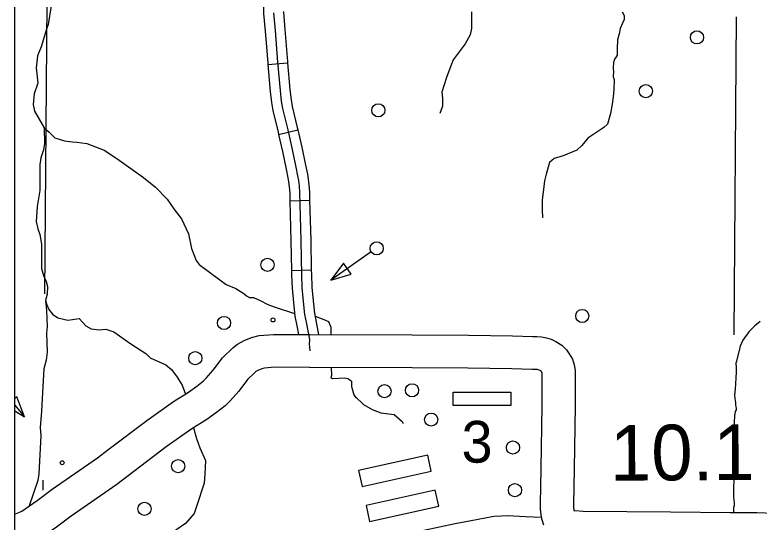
# Model space of a CAD drawing. Extents: x 1382482 to 1385815, y 1168351 to 1170484.
# Drawn here: x 1383432.5 to 1383658.5, y 1168917.8 to 1169071.9 of the extents above; entities that cross this region are included whole.
import ezdxf

# ---------------------------------------------------------------- set-up
doc = ezdxf.new("R2010")
doc.units = 0
for name, color, linetype in [('10', 7, 'Continuous'), ('32', 7, 'Continuous'), ('35', 7, 'Continuous'), ('45', 7, 'Continuous'), ('48', 7, 'Continuous'), ('5', 7, 'Continuous'), ('57', 7, 'Continuous'), ('Default', 7, 'Continuous'), ('R_No Plot', 7, 'Continuous')]:
    doc.layers.add(name, color=color, linetype=linetype)

msp = doc.modelspace()

# ---------------------------------------------------------------- linework, layer by layer
at = {"layer": '10'}
for points in [[(1383432.46, 1168920.31), (1383432.63, 1168920.36), (1383433.63, 1168920.76), (1383434.55, 1168921.19), (1383439.25, 1168924.44), (1383443.77, 1168927.8), (1383457.54, 1168937.33), (1383460.72, 1168939.82), (1383472.51, 1168948.72), (1383480.67, 1168954.51), (1383485.15, 1168957.33), (1383487.72, 1168959.15), (1383489.71, 1168960.71), (1383490.59, 1168961.56), (1383492.7, 1168963.95), (1383495.54, 1168967.72), (1383498.61, 1168970.75), (1383500.11, 1168971.91), (1383502.05, 1168973.01), (1383504.32, 1168973.93), (1383506.65, 1168974.52), (1383510.95, 1168974.84), (1383521.99, 1168974.83)], [(1383522.01, 1168974.83), (1383553.13, 1168974.67), (1383570.17, 1168974.58), (1383583.6, 1168974.37), (1383589.71, 1168974.19), (1383591, 1168974.19), (1383592.4, 1168974.11), (1383593.95, 1168973.8), (1383595.35, 1168973.34), (1383596.69, 1168972.73), (1383598.53, 1168971.58), (1383599.93, 1168970.13), (1383600.81, 1168968.92), (1383601.76, 1168967.34), (1383602.33, 1168965.56), (1383602.62, 1168963.85), (1383602.62, 1168953.1), (1383602.29, 1168933.97), (1383602.11, 1168923.26), (1383602.09, 1168922.27), (1383602.19, 1168921.55), (1383602.21, 1168921.41), (1383602.53, 1168921.33), (1383605.02, 1168921.21), (1383631.59, 1168920.93), (1383649.64, 1168920.79), (1383657.78, 1168920.79), (1383662.89, 1168920.53)], [(1383521.98, 1168964.83), (1383511.31, 1168964.84), (1383508.27, 1168964.62), (1383507.46, 1168964.41), (1383506.41, 1168963.98), (1383505.66, 1168963.56), (1383505.2, 1168963.2), (1383503.08, 1168961.11), (1383500.45, 1168957.63), (1383497.81, 1168954.64), (1383496.28, 1168953.16), (1383493.7, 1168951.14), (1383490.71, 1168949.02), (1383486.23, 1168946.19), (1383478.41, 1168940.65), (1383466.82, 1168931.89), (1383463.46, 1168929.28), (1383449.6, 1168919.68), (1383445.08, 1168916.32), (1383439.56, 1168912.49), (1383437.61, 1168911.58), (1383435.92, 1168910.91), (1383433.89, 1168910.3), (1383432.46, 1168909.98)], [(1383593.05, 1168916.9), (1383592.47, 1168918.86), (1383592.29, 1168920.17), (1383592.08, 1168921.67), (1383592.11, 1168923.44), (1383592.29, 1168934.14), (1383592.62, 1168953.19), (1383592.62, 1168963.03), (1383592.59, 1168963.18), (1383592.46, 1168963.4), (1383592.25, 1168963.69), (1383592.19, 1168963.75), (1383591.96, 1168963.89), (1383591.7, 1168964.01), (1383591.38, 1168964.12), (1383591.12, 1168964.17), (1383590.71, 1168964.19), (1383589.56, 1168964.19), (1383583.37, 1168964.38), (1383570.06, 1168964.58), (1383553.08, 1168964.67), (1383521.96, 1168964.83)]]:
    msp.add_lwpolyline(points, dxfattribs=at)
at = {"layer": '32'}
for p, q in [((1383509.3, 1169056.83), (1383515.28, 1169057.32)), ((1383512.55, 1169035.58), (1383518.4, 1169036.91)), ((1383515.97, 1169015.38), (1383521.97, 1169015.55)), ((1383516.48, 1168994.29), (1383522.48, 1168994.41))]:
    msp.add_line(p, q, dxfattribs=at)
for points in [[(1383513.92, 1169078.81), (1383512.25, 1169078.78), (1383510.72, 1169078.4), (1383508.66, 1169077.09), (1383507.99, 1169075.21), (1383507.92, 1169073.98), (1383508, 1169072.27), (1383508.47, 1169066.91), (1383509.27, 1169057.25), (1383509.3, 1169056.83)], [(1383514, 1169072.81), (1383513.98, 1169072.81), (1383513.99, 1169072.68), (1383514.45, 1169067.42), (1383515.25, 1169057.74), (1383515.28, 1169057.32)], [(1383510.99, 1169072.47), (1383511.46, 1169067.16), (1383512.26, 1169057.49), (1383512.97, 1169048.87), (1383513.36, 1169045.7), (1383513.72, 1169043.41), (1383515.3, 1169036.98), (1383516.66, 1169031.03), (1383517.76, 1169025.57), (1383518.33, 1169022.94), (1383518.55, 1169021.55), (1383518.76, 1169019.91), (1383518.9, 1169017.88), (1383519.29, 1169003.33), (1383519.51, 1168992.92), (1383519.65, 1168989.03), (1383520.03, 1168984.78), (1383520.43, 1168980.83), (1383521.04, 1168978.02), (1383521.89, 1168973.27), (1383521.86, 1168971.85), (1383521.98, 1168969.83)], [(1383509.3, 1169056.83), (1383509.99, 1169048.56), (1383510.39, 1169045.28), (1383510.77, 1169042.82), (1383512.38, 1169036.29), (1383512.55, 1169035.58)], [(1383515.28, 1169057.32), (1383515.96, 1169049.18), (1383516.33, 1169046.11), (1383516.66, 1169044.01), (1383518.22, 1169037.67), (1383518.4, 1169036.91)], [(1383518.4, 1169036.91), (1383519.59, 1169031.66), (1383520.7, 1169026.19), (1383521.28, 1169023.48), (1383521.52, 1169021.97), (1383521.75, 1169020.21), (1383521.9, 1169018.02), (1383521.97, 1169015.55)], [(1383512.55, 1169035.58), (1383513.73, 1169030.4), (1383514.83, 1169024.96), (1383515.38, 1169022.39), (1383515.58, 1169021.12), (1383515.77, 1169019.61), (1383515.91, 1169017.73), (1383515.97, 1169015.38)], [(1383515.97, 1169015.38), (1383516.3, 1169003.25), (1383516.48, 1168994.29)], [(1383521.97, 1169015.55), (1383522.29, 1169003.4), (1383522.48, 1168994.41)], [(1383516.48, 1168994.29), (1383516.51, 1168992.83), (1383516.66, 1168988.84), (1383517.04, 1168984.49), (1383517.47, 1168980.36), (1383518.1, 1168977.44), (1383518.56, 1168974.83)], [(1383522.48, 1168994.41), (1383522.51, 1168993), (1383522.65, 1168989.22), (1383523.01, 1168985.06), (1383523.4, 1168981.3), (1383523.98, 1168978.59), (1383524.66, 1168974.82)]]:
    msp.add_lwpolyline(points, dxfattribs=at)
at = {"layer": '35'}
for points in [[(1383443.44, 1169074.62), (1383442.6, 1169068.89), (1383442.1, 1169067.52), (1383440.46, 1169062.14), (1383439.32, 1169059.45), (1383438.88, 1169055.8), (1383439.47, 1169051.08), (1383438.3, 1169047.87), (1383438.05, 1169044.66), (1383438.46, 1169042.58), (1383441.34, 1169037.6), (1383442.87, 1169036.21), (1383444.61, 1169034.53), (1383447.57, 1169033.62), (1383449.96, 1169033.32), (1383451.24, 1169033.24), (1383454.31, 1169032.85), (1383459.59, 1169030.74), (1383463.46, 1169028.26), (1383471.55, 1169022.45), (1383475.19, 1169019.57), (1383478.71, 1169015.87), (1383480.9, 1169012.68), (1383483.03, 1169009.95), (1383485.15, 1169005.4), (1383486.14, 1169000.92), (1383487.5, 1168997.32), (1383488.41, 1168996.1), (1383494.7, 1168991.37), (1383496.63, 1168989.94), (1383499.52, 1168988.75), (1383501.98, 1168987.27), (1383502.78, 1168986.51), (1383503.69, 1168986.09), (1383504.94, 1168986.01), (1383506.93, 1168985.14), (1383509.25, 1168983.9), (1383511.24, 1168983.18), (1383517.38, 1168981.23)], [(1383571.08, 1169072.75), (1383571.08, 1169067.73), (1383570.77, 1169065.82), (1383569.24, 1169063.06), (1383565.59, 1169058.2), (1383564.86, 1169056.42), (1383563.5, 1169052.88), (1383562.12, 1169048.36), (1383562.35, 1169046.52), (1383562.28, 1169044.15), (1383561.51, 1169041.93)], [(1383616.93, 1169072.75), (1383617.45, 1169071.66), (1383617.45, 1169070.45), (1383616.99, 1169069.31), (1383616.28, 1169067.71), (1383615.92, 1169066.1), (1383615.46, 1169064.25), (1383615.39, 1169061.51), (1383615.39, 1169059.59), (1383615.01, 1169059.14), (1383614.55, 1169058.43), (1383614.23, 1169057.4), (1383614.12, 1169055.76), (1383614.23, 1169054.33), (1383614.16, 1169053.55), (1383614.12, 1169053.05), (1383614.48, 1169052.2), (1383614.38, 1169049.17), (1383614.12, 1169046.96), (1383613.82, 1169044.72), (1383613.34, 1169041.92), (1383612.41, 1169038.71), (1383611.35, 1169037.64), (1383607.95, 1169035.48), (1383606.44, 1169034.42), (1383604.65, 1169032.16), (1383603.09, 1169030.81), (1383599.01, 1169029.06), (1383596.22, 1169028.28), (1383594.79, 1169027.03), (1383593.85, 1169023.45), (1383593.31, 1169021.46), (1383592.89, 1169018), (1383592.6, 1169015.72), (1383592.6, 1169012.8), (1383592.67, 1169010.28)], [(1383441.34, 1169037.6), (1383441.46, 1169032.83), (1383441.12, 1169030.87), (1383440.34, 1169028.42), (1383440.03, 1169026.42), (1383440.02, 1169018.53), (1383439.26, 1169013.67), (1383438.94, 1169009.1), (1383439.4, 1169006.87), (1383440.05, 1169005.19), (1383440.51, 1169002.19), (1383440.57, 1168994.82), (1383441.11, 1168992.7), (1383441.92, 1168990.95), (1383442.38, 1168989.35), (1383442.31, 1168987.02), (1383441.77, 1168985.18), (1383442.14, 1168983.78), (1383442.79, 1168982.38), (1383443.92, 1168980.99), (1383445.53, 1168979.84), (1383448.57, 1168979.18), (1383451.96, 1168979.69), (1383453.98, 1168977.47), (1383455.59, 1168976.52), (1383458.03, 1168976.18), (1383460.1, 1168976.43), (1383462.51, 1168975.57), (1383467.65, 1168971.93), (1383472.27, 1168969), (1383473.56, 1168967.69), (1383478.29, 1168965.61), (1383479.98, 1168964.22), (1383481.76, 1168961.87), (1383483.3, 1168959.44), (1383484.32, 1168956.74)], [(1383441.77, 1168985.18), (1383442.08, 1168982.1), (1383442.27, 1168977.21), (1383442.09, 1168975.25), (1383442.22, 1168969.4), (1383442, 1168967), (1383441.3, 1168964.35), (1383440.7, 1168955.41), (1383440.57, 1168951.53), (1383440.13, 1168946.56), (1383440.31, 1168944.03), (1383439.76, 1168932.48), (1383439.44, 1168930.45), (1383436.82, 1168922.76)], [(1383523.61, 1168980.36), (1383526.24, 1168979.35), (1383527.65, 1168978.78), (1383528.36, 1168977), (1383528.42, 1168974.8)], [(1383658.8, 1168978.76), (1383657.17, 1168977.47), (1383655.39, 1168975.61), (1383653.49, 1168973.11), (1383652.75, 1168971.27), (1383651.47, 1168966.35)], [(1383528.5, 1168964.8), (1383528.56, 1168962.37), (1383528.45, 1168961.73), (1383528.88, 1168961.41), (1383532.69, 1168961.66), (1383533.53, 1168961.41), (1383534.17, 1168961.02), (1383534.64, 1168960.59), (1383534.67, 1168958.98), (1383535.38, 1168956.49), (1383536.04, 1168955.6)], [(1383650.75, 1168920.79), (1383650.75, 1168922.33), (1383650.97, 1168922.93), (1383651.01, 1168923.67), (1383650.88, 1168924.53), (1383650.79, 1168925.48), (1383650.79, 1168926.91), (1383650.84, 1168927.86), (1383650.84, 1168928.85), (1383650.88, 1168930.06), (1383650.88, 1168930.84), (1383650.92, 1168931.74), (1383651.27, 1168932.52), (1383651.35, 1168933.04), (1383651.35, 1168933.3), (1383651.18, 1168933.64), (1383651.09, 1168933.9), (1383651.31, 1168934.51), (1383651.31, 1168934.77), (1383651.18, 1168935.2), (1383650.97, 1168935.8), (1383650.97, 1168936.45), (1383650.97, 1168937.1), (1383651.09, 1168938.05), (1383651.09, 1168939.74), (1383651.09, 1168941.03), (1383651.09, 1168942.2), (1383651.01, 1168944.96), (1383651.05, 1168946), (1383651.01, 1168948.18), (1383651.09, 1168950.08), (1383651.31, 1168951.42), (1383651.57, 1168951.98), (1383651.57, 1168952.41), (1383651.53, 1168952.85), (1383651.44, 1168953.49), (1383651.4, 1168954.18), (1383651.18, 1168955.39), (1383651.14, 1168956.39), (1383651.31, 1168958.2), (1383651.44, 1168959.8), (1383651.48, 1168961.7), (1383651.57, 1168963.39), (1383651.61, 1168964.55), (1383651.47, 1168966.35)], [(1383535.79, 1168955.94), (1383538.33, 1168953.54), (1383540.92, 1168952.03), (1383543.63, 1168951.03), (1383547.6, 1168950.51), (1383550.02, 1168948.36), (1383550.39, 1168947.79)], [(1383486.74, 1168946.51), (1383487.59, 1168943.22), (1383488.65, 1168940.38), (1383490.3, 1168936.52), (1383490.16, 1168932.36), (1383489.96, 1168929.64), (1383487.57, 1168922.6), (1383486.91, 1168920.48), (1383484.26, 1168917.42), (1383481.38, 1168915.41), (1383477.77, 1168911.7), (1383476.92, 1168908.65), (1383477.3, 1168906.01), (1383479.69, 1168902.58), (1383481.96, 1168897.99), (1383482.88, 1168893.15), (1383483.45, 1168884.72)]]:
    msp.add_lwpolyline(points, dxfattribs=at)
at = {"layer": '45'}
for points in [[(1383577.41, 1168919.42), (1383571.05, 1168918.22), (1383566.2, 1168917.32), (1383556.63, 1168915.25)], [(1383592.42, 1168919.26), (1383587.53, 1168919.44), (1383582.03, 1168919.7), (1383580.16, 1168919.62), (1383578.05, 1168919.54), (1383577.41, 1168919.42)]]:
    msp.add_lwpolyline(points, dxfattribs=at)
at = {"layer": '5'}
for points in [[(1383442.15, 1169075.79), (1383441.44, 1168987.13)], [(1383651.53, 1169071.27), (1383650.83, 1168974.67)], [(1383440.99, 1168930.54), (1383440.97, 1168927.55)]]:
    msp.add_lwpolyline(points, dxfattribs=at)
at = {"layer": '57'}
for p, q in [((1383557.84, 1168938.14), (1383536.84, 1168933.54)), ((1383558.91, 1168933.26), (1383557.84, 1168938.14)), ((1383536.84, 1168933.54), (1383537.91, 1168928.66)), ((1383537.91, 1168928.66), (1383558.91, 1168933.26)), ((1383560.1, 1168927.53), (1383539.1, 1168922.93)), ((1383561.17, 1168922.65), (1383560.1, 1168927.53)), ((1383539.1, 1168922.93), (1383540.17, 1168918.05)), ((1383540.17, 1168918.05), (1383561.17, 1168922.65))]:
    msp.add_line(p, q, dxfattribs=at)
for points in [[(1383432.46, 1168951.63), (1383435.38, 1168949.82), (1383433.03, 1168955.83), (1383432.46, 1168955.35)], [(1383432.46, 1168953.32), (1383435.38, 1168949.82)]]:
    msp.add_lwpolyline(points, dxfattribs=at)
msp.add_circle((1383446.82, 1168935.87), 0.6, dxfattribs=at)
at = {"layer": 'Default'}
msp.add_lwpolyline([(1383540.7, 1168999.9), (1383528.36, 1168991.28)], dxfattribs=at)
for points in [[(1383534.55, 1168993.11), (1383532.21, 1168996.46), (1383528.36, 1168991.28)], [(1383565.54, 1168953.29), (1383565.54, 1168957.29), (1383583.04, 1168957.29), (1383583.04, 1168953.29)]]:
    msp.add_lwpolyline(points, close=True, dxfattribs=at)
for centre, radius in [((1383639.6, 1169065.03), 2), ((1383624.07, 1169048.69), 2), ((1383542.83, 1169042.89), 2), ((1383542.33, 1169000.97), 2), ((1383509.19, 1168995.95), 2), ((1383604.76, 1168980.44), 2), ((1383495.97, 1168978.32), 2), ((1383510.85, 1168979.22), 0.6), ((1383487.24, 1168967.63), 2), ((1383553.07, 1168957.86), 2), ((1383544.72, 1168957.58), 2), ((1383558.89, 1168948.97), 2), ((1383583.72, 1168940.47), 2), ((1383482.07, 1168934.84), 2), ((1383584.32, 1168927.55), 2), ((1383471.83, 1168921.89), 2)]:
    msp.add_circle(centre, radius, dxfattribs=at)
at = {"layer": 'R_No Plot'}
msp.add_lwpolyline([(1383432.46, 1169579.7), (1384939.88, 1169579.7), (1384939.88, 1168702.36), (1383432.46, 1168702.36)], close=True, dxfattribs=at)

# ---------------------------------------------------------------- texts
at = {"layer": '48'}
msp.add_text('10.1', height=16.896, rotation=0.305, dxfattribs=at).set_placement((1383613.18, 1168930.42))
at = {"layer": 'Default'}
msp.add_text('3', height=12.67, dxfattribs=at).set_placement((1383568.1, 1168935.9))

doc.saveas('drawing.dxf')
